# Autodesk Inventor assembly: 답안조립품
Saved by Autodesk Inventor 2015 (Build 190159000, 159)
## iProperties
Created: 2019-09
Part Number: 답안조립품
Document SubType Name: Assembly
Designer: 1010101
Author: 1010101
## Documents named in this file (10)
- C:\Users\1010101\Desktop\조만경\490904V1031\답안조립품.iam
- C:\Users\1010101\Desktop\조만경\490904V1031\V-벨트풀리.ipt
- C:\Users\1010101\Desktop\조만경\490904V1031\너트 M10x1.ipt
- C:\Users\1010101\Desktop\조만경\490904V1031\베어링 6004.ipt
- C:\Users\1010101\Desktop\조만경\490904V1031\본체.ipt
- C:\Users\1010101\Desktop\조만경\490904V1031\볼트 M4.ipt
- C:\Users\1010101\Desktop\조만경\490904V1031\오일 실 17 30 5.ipt
- C:\Users\1010101\Desktop\조만경\490904V1031\축.ipt
- C:\Users\1010101\Desktop\조만경\490904V1031\커버.ipt
- C:\Users\1010101\Desktop\조만경\490904V1031\키 5 x 5 x 12.ipt
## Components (2 placed, 1 different names)
1. V-벨트풀리:1 — 각도:4
2. V-벨트풀리:2 — 각도:3
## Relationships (2: Angle 2)
- 각도:3 [Angle]: V-벨트풀리:2
- 각도:4 [Angle]: V-벨트풀리:1
